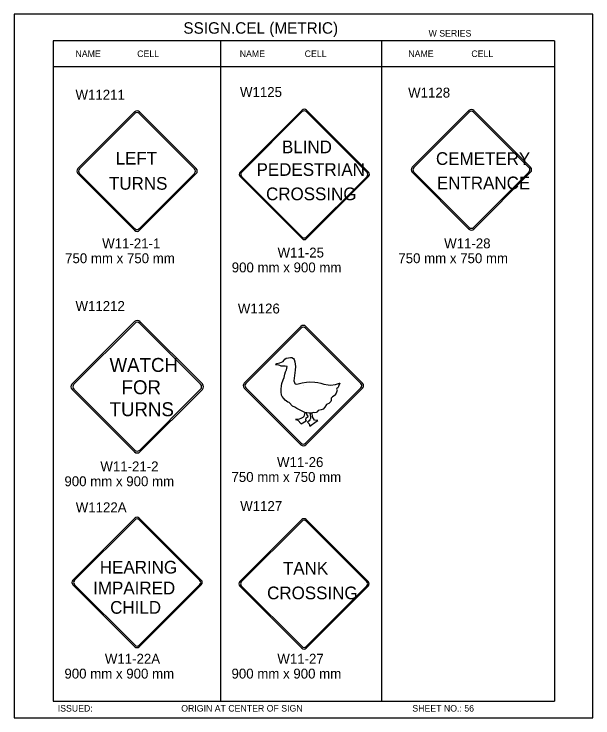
# Model space of a CAD drawing. Extents: x -12 to 6962, y -3756 to 679.
# Drawn here: x 1549.2 to 1724.4, y -465.8 to -252.7 of the extents above; entities that cross this region are included whole.
import ezdxf

# ---------------------------------------------------------------- set-up
doc = ezdxf.new("R2010")
doc.units = 0
for name, color, linetype in [('Level 1', 7, 'Continuous'), ('Level 2', 7, 'Continuous'), ('Level 3', 7, 'Continuous'), ('Level 62', 7, 'Continuous')]:
    doc.layers.add(name, color=color, linetype=linetype)

msp = doc.modelspace()

# ---------------------------------------------------------------- linework, layer by layer
at = {"layer": 'Level 1'}
for p, q in [((1712.82, -260.71), (1561.06, -260.71)), ((1561.06, -260.71), (1561.06, -460.71)), ((1611.65, -260.71), (1611.65, -460.71)), ((1660.43, -260.71), (1660.43, -460.71)), ((1712.82, -260.71), (1712.82, -460.71)), ((1712.82, -268.62), (1561.06, -268.62)), ((1568.48, -299.44), (1585.67, -282.26)), ((1568.98, -299.51), (1585.73, -282.75)), ((1587.1, -282.75), (1603.85, -299.51)), ((1587.17, -282.26), (1604.35, -299.44)), ((1617.6, -300.53), (1636.38, -281.75)), ((1618.05, -300.58), (1636.44, -282.2)), ((1637.67, -282.2), (1656.05, -300.58)), ((1637.72, -281.75), (1656.5, -300.53)), ((1669.72, -299.05), (1686.91, -281.86)), ((1670.22, -299.11), (1686.97, -282.36)), ((1688.34, -282.36), (1705.09, -299.11)), ((1688.4, -281.86), (1705.59, -299.05)), ((1586.42, -300.07), (1586.42, -300.07)), ((1687.66, -299.68), (1687.66, -299.68)), ((1585.67, -318.12), (1568.48, -300.94)), ((1585.73, -317.63), (1568.98, -300.88)), ((1603.85, -300.88), (1587.1, -317.63)), ((1604.35, -300.94), (1587.17, -318.12)), ((1636.38, -320.65), (1617.6, -301.87)), ((1636.44, -320.2), (1618.05, -301.81)), ((1637.23, -301.06), (1637.23, -301.06)), ((1656.05, -301.81), (1637.67, -320.2)), ((1656.5, -301.87), (1637.72, -320.65)), ((1686.91, -317.73), (1669.72, -300.54)), ((1686.97, -317.23), (1670.22, -300.48)), ((1705.09, -300.48), (1688.34, -317.23)), ((1705.59, -300.54), (1688.4, -317.73)), ((1566.76, -364.65), (1585.67, -345.75)), ((1567.31, -364.72), (1585.73, -346.3)), ((1587.24, -346.3), (1605.67, -364.72)), ((1587.31, -345.75), (1606.22, -364.65)), ((1618.85, -364.41), (1636.03, -347.22)), ((1637.53, -347.22), (1654.72, -364.41)), ((1619.35, -364.47), (1636.1, -347.72)), ((1637.47, -347.72), (1654.22, -364.47)), ((1585.67, -385.2), (1566.76, -366.3)), ((1585.74, -384.65), (1567.31, -366.23)), ((1586.49, -365.47), (1586.49, -365.47)), ((1605.67, -366.23), (1587.24, -384.65)), ((1606.22, -366.3), (1587.31, -385.2)), ((1636.03, -383.09), (1618.85, -365.9)), ((1636.1, -382.59), (1619.35, -365.84)), ((1636.78, -365.04), (1636.78, -365.04)), ((1654.22, -365.84), (1637.47, -382.59)), ((1654.72, -365.9), (1637.53, -383.09)), ((1566.98, -424.07), (1585.76, -405.29)), ((1567.43, -424.12), (1585.82, -405.74)), ((1587.05, -405.74), (1605.43, -424.12)), ((1587.1, -405.29), (1605.88, -424.07)), ((1617.54, -424.49), (1636.32, -405.71)), ((1617.99, -424.55), (1636.37, -406.16)), ((1637.6, -406.16), (1655.99, -424.55)), ((1637.66, -405.71), (1656.44, -424.49)), ((1585.76, -444.19), (1566.98, -425.41)), ((1585.82, -443.74), (1567.43, -425.35)), ((1586.61, -424.6), (1586.61, -424.6)), ((1605.43, -425.35), (1587.05, -443.74)), ((1605.88, -425.41), (1587.1, -444.19)), ((1636.32, -444.61), (1617.54, -425.83)), ((1636.37, -444.16), (1617.99, -425.78)), ((1637.17, -425.02), (1637.17, -425.02)), ((1655.99, -425.78), (1637.6, -444.16)), ((1656.44, -425.83), (1637.66, -444.61)), ((1561.06, -460.71), (1712.82, -460.71))]:
    msp.add_line(p, q, dxfattribs=at)
for points in [[(1628.32, -358.79), (1628.51, -358.55), (1628.76, -358.46), (1629.61, -358.24), (1630.67, -357.83), (1630.83, -357.52), (1631.17, -357.15), (1631.61, -356.86), (1632.27, -356.71), (1632.89, -356.65), (1633.3, -356.68), (1633.77, -356.96), (1633.96, -357.24), (1634.21, -357.96), (1634.33, -358.65), (1634.39, -359.33), (1634.27, -360.49), (1633.92, -363.65), (1634.08, -364.18), (1634.24, -364.46), (1634.32, -364.63), (1634.77, -364.74), (1635.17, -364.65), (1636.43, -364.31), (1637.68, -364.09), (1638.68, -363.99), (1640.24, -364.06), (1641.12, -364.18), (1642.08, -364.37), (1642.99, -364.71), (1644.27, -364.87), (1644.99, -365.02), (1646.49, -364.81), (1647.68, -364.43), (1647.78, -364.43), (1647.56, -365.12), (1647.4, -365.46), (1647.25, -365.84), (1646.93, -366.06), (1646.78, -366.19), (1646.99, -366.62), (1646.96, -366.87), (1646.68, -367.46), (1646.34, -368), (1646.06, -368.25), (1645.62, -368.59), (1645.21, -368.93), (1645.18, -369.28), (1645.18, -369.62), (1645.12, -369.93), (1644.87, -370.18), (1644.49, -370.53), (1643.96, -370.72), (1643.77, -370.84), (1643.27, -371.69), (1642.74, -372.31), (1642.15, -372.5), (1641.24, -372.69), (1640.99, -373.12), (1640.9, -373.15), (1640.68, -373.25), (1640.21, -373.37), (1639.8, -373.31), (1639.18, -373.44), (1638.52, -373.44), (1637.86, -373.37), (1637.24, -373.25), (1636.61, -372.94), (1635.77, -372.56), (1634.8, -372.06), (1634.17, -371.69), (1633.52, -371.34), (1632.45, -370.25), (1632.08, -370.12), (1631.64, -369.81), (1631.23, -369.5), (1630.83, -369.06), (1630.38, -368.46), (1630.14, -368), (1630.01, -367.03), (1630.08, -366.18), (1630.17, -365.24), (1630.3, -364.49), (1630.64, -363.43), (1630.92, -362.65), (1631.14, -361.71), (1631.36, -361.02), (1631.7, -360.37), (1631.92, -359.33), (1631.23, -359.3), (1630.55, -359.3), (1630.08, -359.27), (1629.7, -359.05), (1629.36, -358.96), (1628.89, -358.9), (1628.39, -358.87)], [(1637.24, -373.28), (1636.93, -374.47), (1636.61, -374.78), (1636.02, -375.12), (1635.46, -375.31), (1634.42, -375.38), (1635.14, -375.63), (1636.08, -376.72), (1637.58, -375.84), (1637.71, -375.81), (1637.55, -375.56), (1637.58, -374.87), (1638.24, -374.53), (1638.24, -374.37), (1637.86, -373.9), (1637.74, -373.59), (1637.74, -373.35)], [(1638.83, -373.44), (1638.93, -375.06), (1638.77, -375.5), (1638.52, -375.78), (1637.99, -376.19), (1638.52, -376.75), (1638.74, -377.41), (1640.65, -375.97), (1641.15, -375.72), (1640.71, -375.72), (1640.18, -375.59), (1639.58, -374.62), (1639.42, -373.39)]]:
    msp.add_lwpolyline(points, dxfattribs=at)
for centre, radius, start, end in [((1586.42, -283), 1.06, 45, 135), ((1586.42, -283.44), 0.969, 45, 135), ((1637.05, -282.42), 0.948, 45, 135), ((1637.05, -282.81), 0.869, 45, 135), ((1687.65, -282.61), 1.06, 45, 135), ((1687.65, -283.04), 0.969, 45, 135), ((1569.23, -300.19), 1.06, 135, 225), ((1569.67, -300.19), 0.969, 135, 225), ((1603.17, -300.19), 0.969, 315, 45), ((1603.6, -300.19), 1.06, 315, 45), ((1670.47, -299.79), 1.06, 135, 225), ((1670.9, -299.79), 0.969, 135, 225), ((1704.4, -299.79), 0.969, 315, 45), ((1704.84, -299.79), 1.06, 315, 45), ((1618.27, -301.2), 0.948, 135, 225), ((1618.67, -301.2), 0.869, 135, 225), ((1655.44, -301.2), 0.869, 315, 45), ((1655.83, -301.2), 0.948, 315, 45), ((1687.65, -316.54), 0.969, 225, 315), ((1586.42, -317.38), 1.06, 225, 315), ((1586.42, -316.94), 0.969, 225, 315), ((1687.65, -316.98), 1.06, 225, 315), ((1637.05, -319.98), 0.948, 225, 315), ((1637.05, -319.58), 0.869, 225, 315), ((1586.49, -346.57), 1.16, 45, 135), ((1586.49, -347.05), 1.07, 45, 135), ((1636.78, -347.97), 1.06, 45, 135), ((1636.78, -348.41), 0.969, 45, 135), ((1567.58, -365.47), 1.16, 135, 225), ((1568.06, -365.47), 1.07, 135, 225), ((1604.91, -365.48), 1.07, 315, 45), ((1605.39, -365.48), 1.16, 315, 45), ((1619.59, -365.16), 1.06, 135, 225), ((1620.03, -365.16), 0.969, 135, 225), ((1653.53, -365.16), 0.969, 315, 45), ((1653.97, -365.16), 1.06, 315, 45), ((1636.78, -382.34), 1.06, 225, 315), ((1636.78, -381.91), 0.969, 225, 315), ((1586.49, -384.38), 1.16, 225, 315), ((1586.49, -383.9), 1.07, 225, 315), ((1586.43, -405.96), 0.948, 45, 135), ((1586.43, -406.35), 0.869, 45, 135), ((1636.99, -406.38), 0.948, 45, 135), ((1636.99, -406.77), 0.869, 45, 135), ((1567.66, -424.74), 0.948, 135, 225), ((1568.05, -424.74), 0.869, 135, 225), ((1604.82, -424.74), 0.869, 315, 45), ((1605.21, -424.74), 0.948, 315, 45), ((1618.21, -425.16), 0.948, 135, 225), ((1618.6, -425.16), 0.869, 135, 225), ((1655.38, -425.16), 0.869, 315, 45), ((1655.77, -425.16), 0.948, 315, 45), ((1586.43, -443.52), 0.948, 225, 315), ((1586.43, -443.13), 0.869, 225, 315), ((1636.99, -443.94), 0.948, 225, 315), ((1636.99, -443.55), 0.869, 225, 315)]:
    msp.add_arc(centre, radius, start, end, dxfattribs=at)
at = {"layer": 'Level 62'}
msp.add_lwpolyline([(1549.19, -465.75), (1724.45, -465.75), (1724.45, -252.66), (1549.19, -252.66)], close=True, dxfattribs=at)

# ---------------------------------------------------------------- texts
at = {"layer": 'Level 1'}
for s, height, p in [('BLIND', 3.841, (1630.29, -294.79)), ('LEFT', 3.841, (1579.94, -298.22)), ('CEMETERY', 3.841, (1676.92, -298.33)), ('PEDESTRIAN', 3.841, (1622.6, -301.64)), ('TURNS', 3.841, (1577.91, -305.84)), ('ENTRANCE', 3.841, (1677.21, -305.7)), ('CROSSING', 3.841, (1625.47, -309.01)), ('WATCH', 4.225, (1578.09, -361)), ('FOR', 4.225, (1581.73, -367.75)), ('TURNS', 4.225, (1578.11, -374.4)), ('HEARING', 3.842, (1575.15, -422.04)), ('TANK', 3.841, (1630.59, -422.34)), ('IMPAIRED', 3.842, (1573.14, -428.34)), ('CROSSING', 3.842, (1625.8, -429.83)), ('CHILD', 3.842, (1578.28, -434.21))]:
    msp.add_text(s, height=height, dxfattribs=at).set_placement(p)
at = {"layer": 'Level 2'}
for s, p in [('W1125', (1617.59, -277.76)), ('W1128', (1668.5, -277.93)), ('W11211', (1567.79, -278.58)), ('W11212', (1567.79, -342.54)), ('W1126', (1616.94, -343.31)), ('W1122A', (1567.87, -403.49)), ('W1127', (1617.66, -403.11))]:
    msp.add_text(s, height=3, dxfattribs=at).set_placement(p)
at = {"layer": 'Level 3'}
for s, height, p in [('SSIGN.CEL (METRIC)', 3.4642, (1600.45, -258.6)), ('W SERIES', 1.979, (1674.69, -259.47)), ('NAME', 1.98, (1567.78, -265.66)), ('CELL', 1.98, (1586.46, -265.66)), ('NAME', 1.98, (1617.51, -265.66)), ('CELL', 1.98, (1637.17, -265.66)), ('NAME', 1.98, (1668.56, -265.66)), ('CELL', 1.98, (1687.64, -265.66)), ('W11-21-1', 3, (1575.86, -323.58)), ('W11-28', 3, (1679.41, -323.58)), ('W11-25', 3, (1628.97, -326.36)), ('750 mm x 750 mm', 3, (1564.64, -328.08)), ('750 mm x 750 mm', 3, (1665.53, -328.08)), ('900 mm x 900 mm', 3, (1615.09, -330.86)), ('W11-26', 3, (1628.8, -389.8)), ('W11-21-2', 3, (1575.31, -391.1)), ('750 mm x 750 mm', 3, (1615.01, -394.3)), ('900 mm x 900 mm', 3, (1564.43, -395.6)), ('W11-22A', 3, (1576.68, -449.34)), ('W11-27', 3, (1628.9, -449.34)), ('900 mm x 900 mm', 3, (1564.43, -453.84)), ('900 mm x 900 mm', 3, (1615.02, -453.84)), ('ISSUED:', 1.98, (1562.41, -463.83)), ('ORIGIN AT CENTER OF SIGN', 1.9795, (1599.79, -463.83)), ('SHEET NO.: 56', 1.9795, (1669.77, -463.83))]:
    msp.add_text(s, height=height, dxfattribs=at).set_placement(p)

doc.saveas('drawing.dxf')
